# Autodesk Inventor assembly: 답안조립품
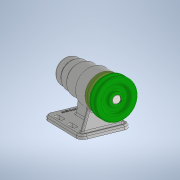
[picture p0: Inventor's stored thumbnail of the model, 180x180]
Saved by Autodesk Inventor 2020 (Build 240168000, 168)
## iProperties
Created: 2021-10
Part Number: 답안조립품
Document SubType Name: Assembly
Designer: user
Author: user
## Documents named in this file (12)
- C:\Users\user\Desktop\711007V1009\답안조립품.iam
- C:\Users\user\Desktop\711007V1009\V벨트풀리.ipt
- C:\Users\user\Desktop\711007V1009\멈춤나사 M3.ipt
- C:\Users\user\Desktop\711007V1009\베어링 6004.ipt
- C:\Users\user\Desktop\711007V1009\베어링 51202.ipt
- C:\Users\user\Desktop\711007V1009\본체.ipt
- C:\Users\user\Desktop\711007V1009\볼트 M4.ipt
- C:\Users\user\Desktop\711007V1009\어댑터슬리브.ipt
- C:\Users\user\Desktop\711007V1009\오일 실 20x35x7.ipt
- C:\Users\user\Desktop\711007V1009\축.ipt
- C:\Users\user\Desktop\711007V1009\커버.ipt
- C:\Users\user\Desktop\711007V1009\키 5x5.ipt
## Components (1 placed, 1 different names)
1. V벨트풀리:1
